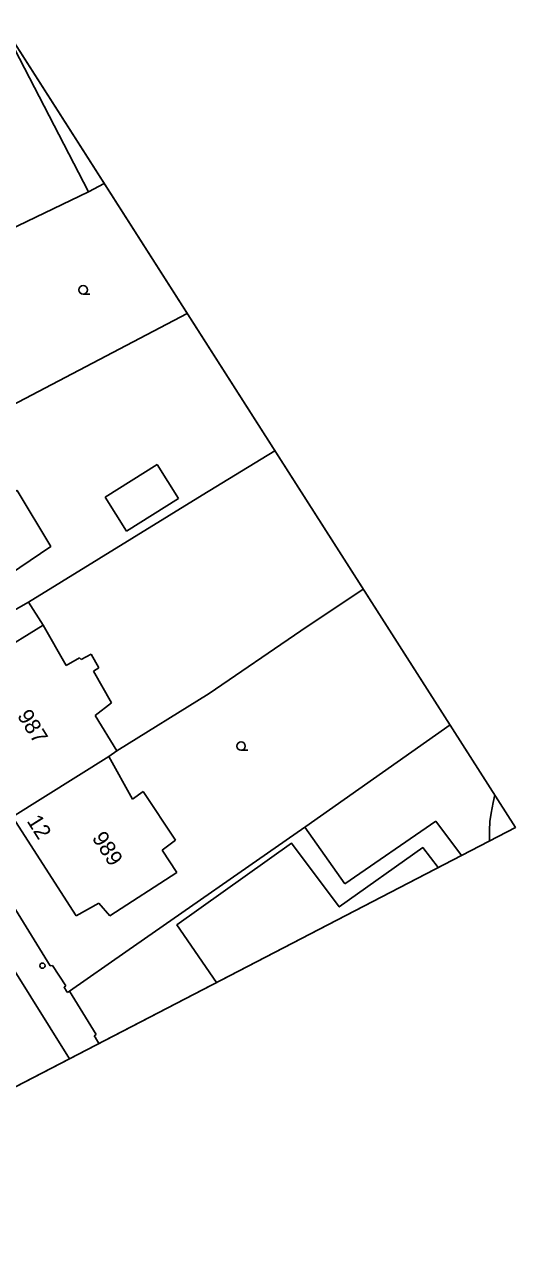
# Model space of a CAD drawing. Extents: x -493753 to -49290, y -1127285 to -112654.
# Drawn here: x -492784.3 to -492737.6, y -1126908.9 to -1126792.4 of the extents above; entities that cross this region are included whole.
import ezdxf

# ---------------------------------------------------------------- set-up
doc = ezdxf.new("R2010")
doc.units = 0
for name, color, linetype in [('Vrstva 1', 7, 'Continuous'), ('Vrstva 10', 7, 'Continuous'), ('Vrstva 11', 7, 'Continuous'), ('Vrstva 28', 7, 'Continuous'), ('Vrstva 36', 7, 'Continuous'), ('Vrstva 43', 7, 'Continuous'), ('Vrstva 44', 7, 'Continuous'), ('Vrstva 5', 7, 'Continuous'), ('Vrstva 60', 7, 'Continuous'), ('Vrstva 7', 7, 'Continuous'), ('Vrstva 8', 7, 'Continuous')]:
    doc.layers.add(name, color=color, linetype=linetype)

msp = doc.modelspace()

# ---------------------------------------------------------------- linework, layer by layer
at = {"layer": 'Vrstva 1'}
msp.add_lwpolyline([(-493753.129, -1126773.634), (-493540.881, -1127284.865), (-492737.61, -1126868.64), (-492950.39, -1126535.73)], dxfattribs=at)
at = {"layer": 'Vrstva 10'}
msp.add_line((-492785.53, -1126881.78), (-492780.015, -1126890.613), dxfattribs=at)
at = {"layer": 'Vrstva 11'}
for points in [[(-492778.19, -1126808.27), (-492786.16, -1126792.91)], [(-492776.699, -1126807.482), (-492778.19, -1126808.27)], [(-492809.19, -1126823.14), (-492778.19, -1126808.27)], [(-492768.809, -1126819.827), (-492790.06, -1126830.92)], [(-492760.477, -1126832.863), (-492767.38, -1126837.09)], [(-492776.61, -1126837.28), (-492771.67, -1126834.16)], [(-492771.67, -1126834.16), (-492769.65, -1126837.38)], [(-492767.38, -1126837.09), (-492783.91, -1126847.23)], [(-492774.59, -1126840.49), (-492776.61, -1126837.28)], [(-492769.65, -1126837.38), (-492774.59, -1126840.49)], [(-492752.078, -1126846.003), (-492758.01, -1126849.96)], [(-492789.3, -1126850.28), (-492783.91, -1126847.23)], [(-492783.91, -1126847.23), (-492782.51, -1126849.44)], [(-492758.01, -1126849.96), (-492766.72, -1126855.92)], [(-492766.72, -1126855.92), (-492775.5, -1126861.37)], [(-492743.833, -1126858.904), (-492757.53, -1126868.54)], [(-492739.583, -1126865.553), (-492739.73, -1126866.26)], [(-492739.73, -1126866.26), (-492739.92, -1126867.29)], [(-492745.17, -1126868.05), (-492753.82, -1126873.99)], [(-492742.737, -1126871.296), (-492745.17, -1126868.05)], [(-492740.04, -1126868.08), (-492740.07, -1126868.92)], [(-492739.92, -1126867.29), (-492740.04, -1126868.08)], [(-492757.64, -1126868.62), (-492774.66, -1126880.47)], [(-492757.53, -1126868.54), (-492757.64, -1126868.62)], [(-492757.64, -1126868.62), (-492753.82, -1126873.99)], [(-492740.07, -1126868.92), (-492740.07, -1126869.915)]]:
    msp.add_lwpolyline(points, dxfattribs=at)
at = {"layer": 'Vrstva 28'}
msp.add_circle((-492782.58, -1126881.77), 0.25, dxfattribs=at)
at = {"layer": 'Vrstva 36'}
for p, q in [((-492778.712, -1126817.98), (-492778.062, -1126817.977)), ((-492763.702, -1126861.31), (-492763.052, -1126861.307))]:
    msp.add_line(p, q, dxfattribs=at)
for centre in [(-492778.712, -1126817.577), (-492763.701, -1126860.906)]:
    msp.add_circle(centre, 0.403, dxfattribs=at)
at = {"layer": 'Vrstva 5'}
for p, q in [((-492782.51, -1126849.44), (-492792.86, -1126855.75)), ((-492780.31, -1126853.25), (-492782.51, -1126849.44)), ((-492779.06, -1126852.52), (-492780.31, -1126853.25)), ((-492778.9, -1126852.68), (-492779.06, -1126852.52)), ((-492777.94, -1126852.18), (-492778.9, -1126852.68)), ((-492777.23, -1126853.48), (-492777.94, -1126852.18)), ((-492777.72, -1126853.8), (-492777.23, -1126853.48)), ((-492776.01, -1126856.79), (-492777.72, -1126853.8)), ((-492777.58, -1126858), (-492776.01, -1126856.79)), ((-492775.5, -1126861.37), (-492777.58, -1126858)), ((-492776.28, -1126861.9), (-492775.5, -1126861.37)), ((-492772.99, -1126865.22), (-492774.01, -1126865.94)), ((-492769.93, -1126869.85), (-492772.99, -1126865.22)), ((-492785.42, -1126867.64), (-492779.37, -1126877.03)), ((-492771.2, -1126870.8), (-492769.93, -1126869.85)), ((-492769.79, -1126872.93), (-492771.2, -1126870.8)), ((-492776.16, -1126877.05), (-492769.79, -1126872.93)), ((-492779.37, -1126877.03), (-492777.21, -1126875.82)), ((-492777.21, -1126875.82), (-492776.16, -1126877.05))]:
    msp.add_line(p, q, dxfattribs=at)
for points in [[(-492798.46, -1126846.95), (-492798.03, -1126847.63), (-492793.15, -1126844.52), (-492790.75, -1126848.01), (-492781.79, -1126841.94), (-492784.99, -1126836.63), (-492786.28, -1126837.16), (-492786.81, -1126836.05), (-492785.18, -1126834.92), (-492786.2, -1126833.26), (-492788.04, -1126834.04), (-492790.06, -1126830.92)], [(-492785.42, -1126867.64), (-492776.28, -1126861.9)], [(-492774.01, -1126865.94), (-492776.28, -1126861.9)], [(-492766.033, -1126883.368), (-492769.79, -1126877.9), (-492758.9, -1126870.14), (-492754.37, -1126876.19), (-492746.43, -1126870.56), (-492744.959, -1126872.448)]]:
    msp.add_lwpolyline(points, dxfattribs=at)
at = {"layer": 'Vrstva 60'}
msp.add_lwpolyline([(-492991.121, -1127000), (-492737.61, -1126868.64), (-492950.39, -1126535.73), (-493125, -1126587.478)], dxfattribs=at)
at = {"layer": 'Vrstva 7'}
for p, q in [((-492781.83, -1126881.79), (-492789.33, -1126869.69)), ((-492781.62, -1126881.75), (-492781.83, -1126881.79)), ((-492780.19, -1126884.32), (-492780.3, -1126884.18)), ((-492777.67, -1126888.43), (-492777.48, -1126888.31)), ((-492777.58, -1126888.56), (-492777.67, -1126888.43)), ((-492777.205, -1126889.157), (-492777.58, -1126888.56))]:
    msp.add_line(p, q, dxfattribs=at)
for points in [[(-492780.19, -1126884.32), (-492780.01, -1126884.19), (-492774.66, -1126880.47)], [(-492780.3, -1126884.18), (-492780.52, -1126883.82), (-492780.37, -1126883.67)]]:
    msp.add_lwpolyline(points, dxfattribs=at)
at = {"layer": 'Vrstva 8'}
for points in [[(-492780.37, -1126883.67), (-492781.62, -1126881.75)], [(-492780.01, -1126884.19), (-492777.48, -1126888.31)]]:
    msp.add_lwpolyline(points, dxfattribs=at)

# ---------------------------------------------------------------- texts
at = {"layer": 'Vrstva 43'}
for s, rotation, p in [('987', 302.14947, (-492785.024, -1126858.029)), ('989', 302.92689, (-492777.919, -1126869.637))]:
    msp.add_text(s, height=1.5, rotation=rotation, dxfattribs=at).set_placement(p)
at = {"layer": 'Vrstva 44'}
msp.add_text('12', height=1.5, rotation=302.14947, dxfattribs=at).set_placement((-492784.108, -1126868.025))

doc.saveas('drawing.dxf')
